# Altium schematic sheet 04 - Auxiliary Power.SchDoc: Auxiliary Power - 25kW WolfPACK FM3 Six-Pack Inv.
size 431 x 279 mm; Date: 07/2023; DocumentNumber: CRD25DA12N-FMC; Revision: 1.1; SheetNumber: 4; SheetTotal: 8; SheetSize: B
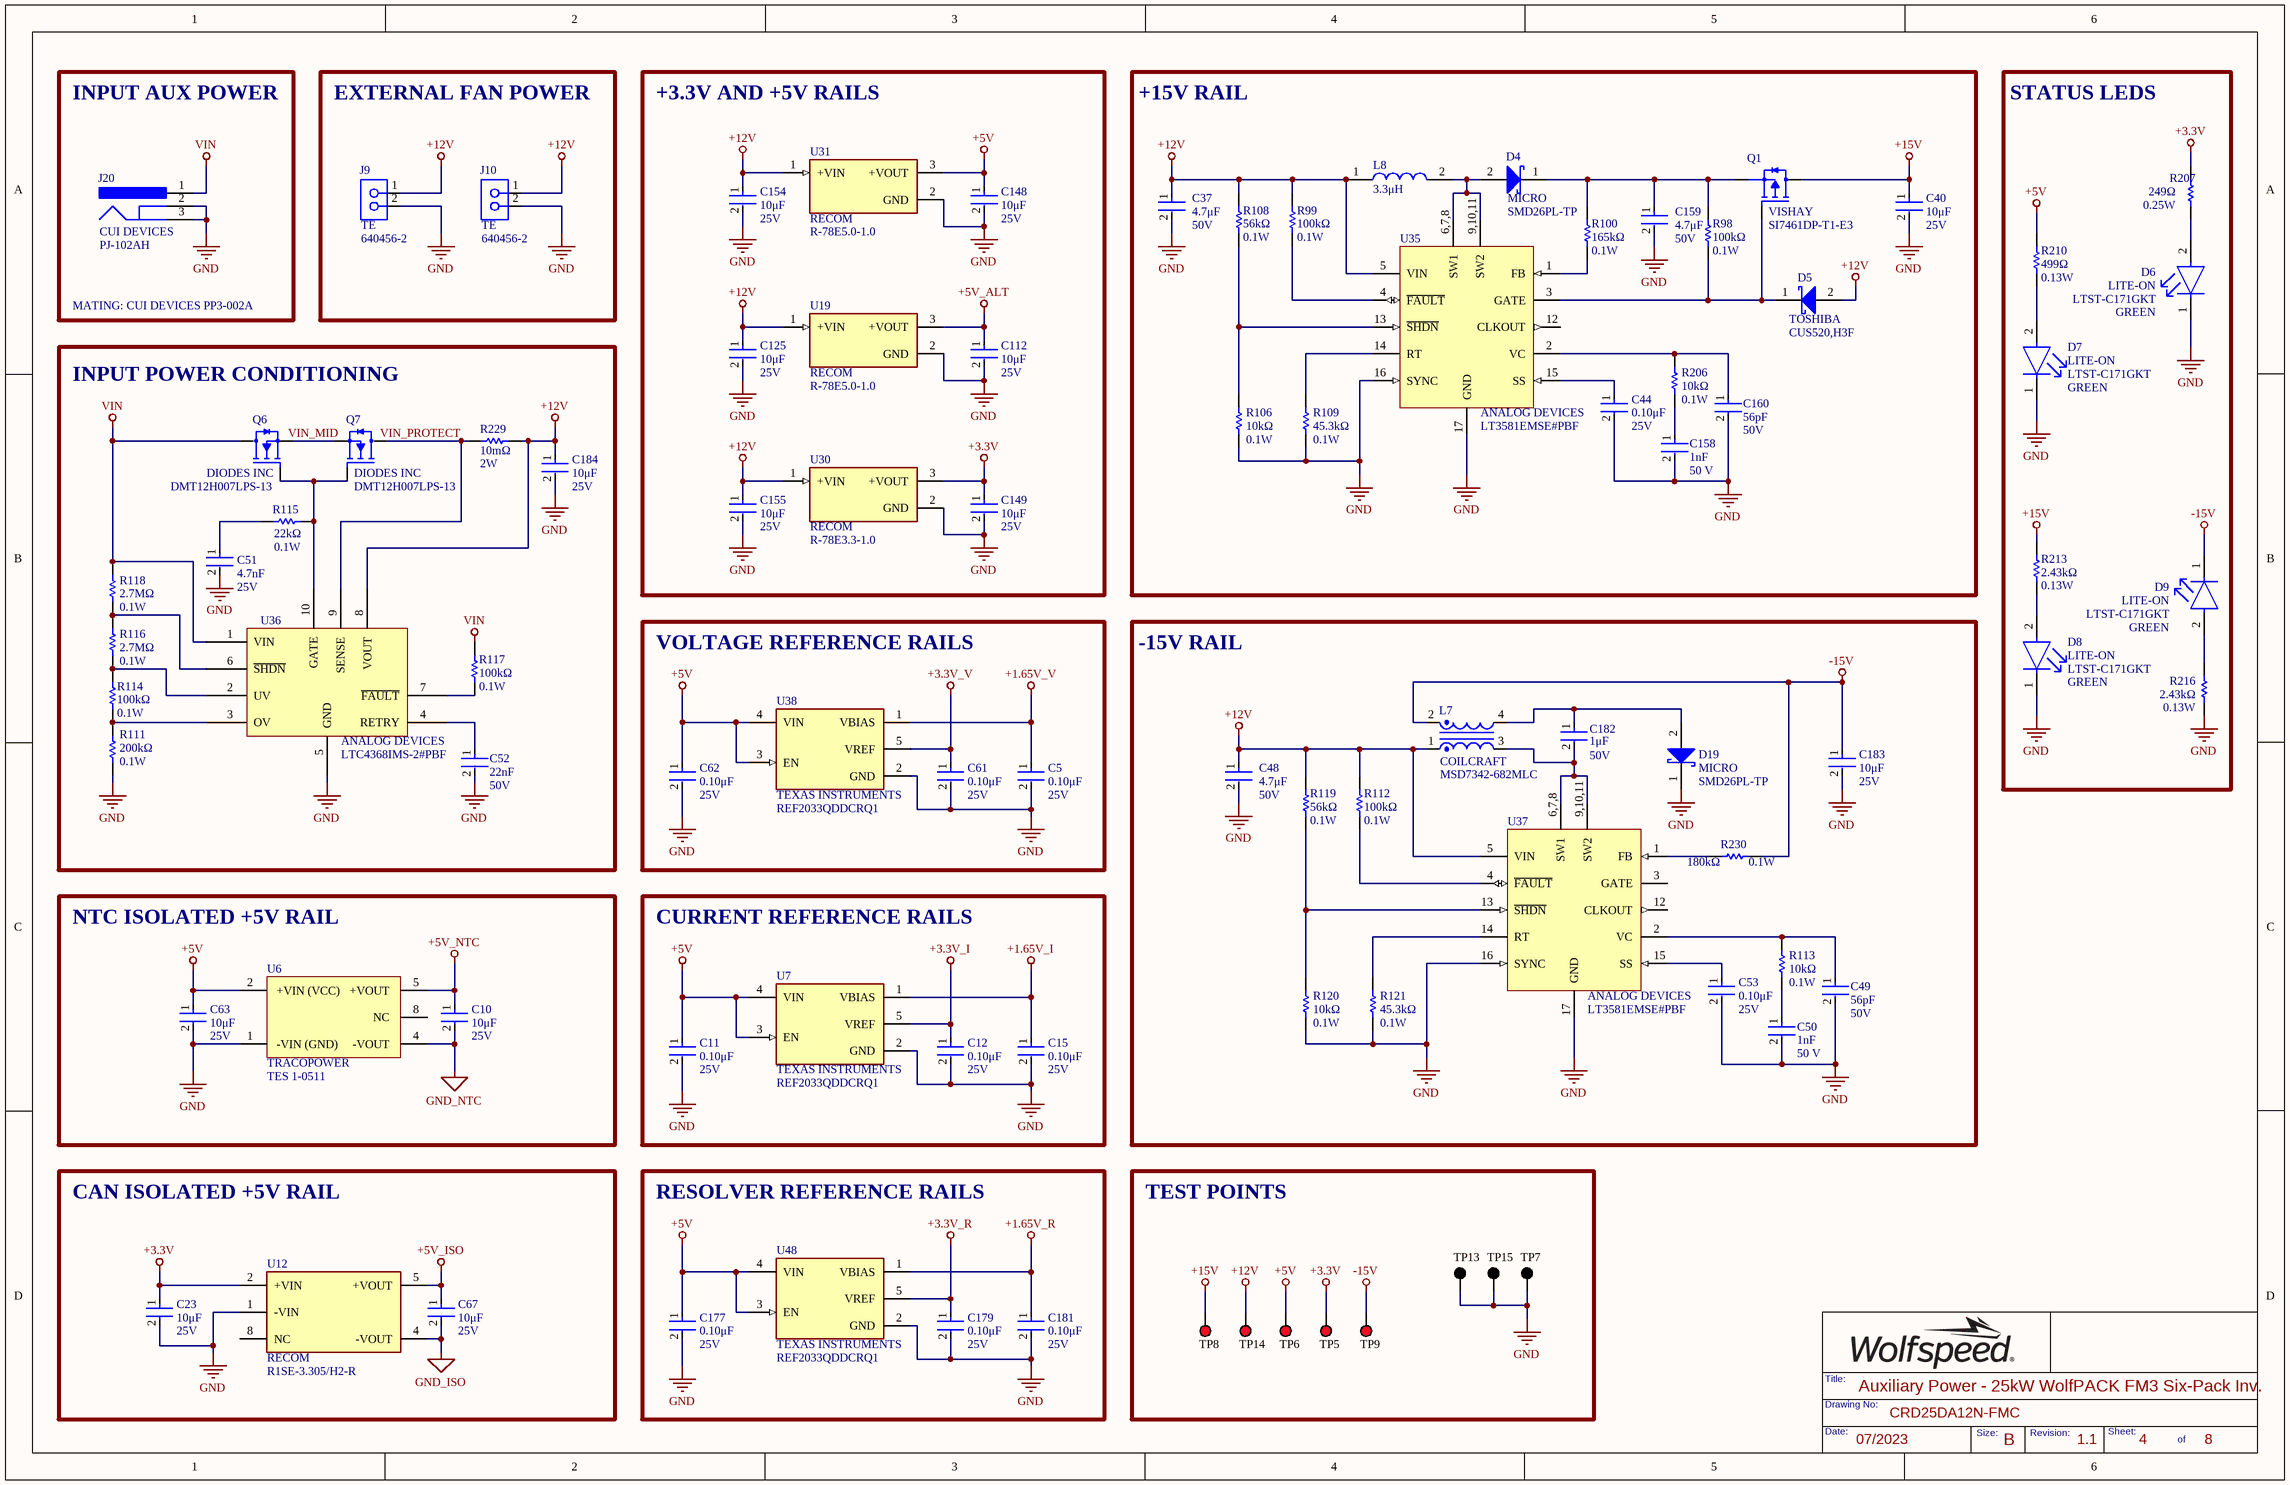
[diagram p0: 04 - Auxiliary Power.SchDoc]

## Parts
C5  Voltage Rating: 25V  Capacitance: 0.10μF  [FP-C0603C-CF-IPC_B]  (hidden comment: C0603C104K3RACTU)
C10  Voltage Rating: 25V  Capacitance: 10μF  [FP-CL31-IPC_B]  (hidden comment: CL31B106KAHSFNE)
C11  Voltage Rating: 25V  Capacitance: 0.10μF  [FP-C0603C-CF-IPC_B]  (hidden comment: C0603C104K3RACTU)
C12  Voltage Rating: 25V  Capacitance: 0.10μF  [FP-C0603C-CF-IPC_B]  (hidden comment: C0603C104K3RACTU)
C15  Voltage Rating: 25V  Capacitance: 0.10μF  [FP-C0603C-CF-IPC_B]  (hidden comment: C0603C104K3RACTU)
C23  Voltage Rating: 25V  Capacitance: 10μF  [FP-CL31-IPC_B]  (hidden comment: CL31B106KAHSFNE)
C37  Voltage Rating: 50V  Capacitance: 4.7μF  [FP-CL31-IPC_C]  (hidden comment: CL31B475KBHNFNE)
C40  Voltage Rating: 25V  Capacitance: 10μF  [FP-CL31-IPC_B]  (hidden comment: CL31B106KAHSFNE)
C44  Voltage Rating: 25V  Capacitance: 0.10μF  [FP-C0603C-CF-IPC_B]  (hidden comment: C0603C104K3RACTU)
C48  Voltage Rating: 50V  Capacitance: 4.7μF  [FP-CL31-IPC_C]  (hidden comment: CL31B475KBHNFNE)
C49  Capacitance: 56pF  Voltage Rating: 50V  [FP-C0603C-CF-IPC_B]  (hidden comment: CL10C560JB8NNNC)
C50  Capacitance: 1nF  Voltage Rating: 50 V  [FP-C0603C-CF-IPC_B]  (hidden comment: C0603C102K5RACAUTO)
C51  Voltage Rating: 25V  Capacitance: 4.7nF  [FP-C0603C-CF-IPC_B]  (hidden comment: C0603C472K3RAC7867)
C52  Capacitance: 22nF  Voltage: 50V  [FP-C0603C-CF-IPC_B]  (hidden comment: CC0805KRX7R9BB223)
C53  Voltage Rating: 25V  Capacitance: 0.10μF  [FP-C0603C-CF-IPC_B]  (hidden comment: C0603C104K3RACTU)
C61  Voltage Rating: 25V  Capacitance: 0.10μF  [FP-C0603C-CF-IPC_B]  (hidden comment: C0603C104K3RACTU)
C62  Voltage Rating: 25V  Capacitance: 0.10μF  [FP-C0603C-CF-IPC_B]  (hidden comment: C0603C104K3RACTU)
C63  Voltage Rating: 25V  Capacitance: 10μF  [FP-CL31-IPC_B]  (hidden comment: CL31B106KAHSFNE)
C67  Voltage Rating: 25V  Capacitance: 10μF  [FP-CL31-IPC_B]  (hidden comment: CL31B106KAHSFNE)
C112  Voltage Rating: 25V  Capacitance: 10μF  [FP-CL31-IPC_B]  (hidden comment: CL31B106KAHSFNE)
C125  Voltage Rating: 25V  Capacitance: 10μF  [FP-CL31-IPC_B]  (hidden comment: CL31B106KAHSFNE)
C148  Voltage Rating: 25V  Capacitance: 10μF  [FP-CL31-IPC_B]  (hidden comment: CL31B106KAHSFNE)
C149  Voltage Rating: 25V  Capacitance: 10μF  [FP-CL31-IPC_B]  (hidden comment: CL31B106KAHSFNE)
C154  Voltage Rating: 25V  Capacitance: 10μF  [FP-CL31-IPC_B]  (hidden comment: CL31B106KAHSFNE)
C155  Voltage Rating: 25V  Capacitance: 10μF  [FP-CL31-IPC_B]  (hidden comment: CL31B106KAHSFNE)
C158  Capacitance: 1nF  Voltage Rating: 50 V  [FP-C0603C-CF-IPC_B]  (hidden comment: C0603C102K5RACAUTO)
C159  Voltage Rating: 50V  Capacitance: 4.7μF  [FP-CL31-IPC_C]  (hidden comment: CL31B475KBHNFNE)
C160  Capacitance: 56pF  Voltage Rating: 50V  [FP-C0603C-CF-IPC_B]  (hidden comment: CL10C560JB8NNNC)
C177  Voltage Rating: 25V  Capacitance: 0.10μF  [FP-C0603C-CF-IPC_B]  (hidden comment: C0603C104K3RACTU)
C179  Voltage Rating: 25V  Capacitance: 0.10μF  [FP-C0603C-CF-IPC_B]  (hidden comment: C0603C104K3RACTU)
C181  Voltage Rating: 25V  Capacitance: 0.10μF  [FP-C0603C-CF-IPC_B]  (hidden comment: C0603C104K3RACTU)
C182  Capacitance: 1μF  Voltage: 50V  [FP-CL21-IPC_A]  (hidden comment: CL21B105KBFNNNE)
C183  Voltage Rating: 25V  Capacitance: 10μF  [FP-CL31-IPC_B]  (hidden comment: CL31B106KAHSFNE)
C184  Voltage Rating: 25V  Capacitance: 10μF  [FP-CL31-IPC_B]  (hidden comment: CL31B106KAHSFNE)
D4  SMD26PL-TP  Manufacturer Print: MICRO  [ONSC-SOD-123FL-2-498-01_V]
D5  CUS520,H3F  Manufacturer Print: TOSHIBA  [FP-USC-MFG]
D6  value GREEN  Manufacturer: LITE-ON  [FP-LTST-C171GKT-MFG]  (hidden comment: LTST-C171GKT)
D7  value GREEN  Manufacturer: LITE-ON  [FP-LTST-C171GKT-MFG]  (hidden comment: LTST-C171GKT)
D8  value GREEN  Manufacturer: LITE-ON  [FP-LTST-C171GKT-MFG]  (hidden comment: LTST-C171GKT)
D9  value GREEN  Manufacturer: LITE-ON  [FP-LTST-C171GKT-MFG]  (hidden comment: LTST-C171GKT)
D19  SMD26PL-TP  Manufacturer Print: MICRO  [ONSC-SOD-123FL-2-498-01_V]
J9  640456-2  Manufacturer Print: TE  [TECO-640456-2_V]
J10  640456-2  Manufacturer Print: TE  [TECO-640456-2_V]
J20  PJ-102AH  Manufacturer Print: CUI DEVICES  [CUI-PJ-102B_V]
L7  MSD7342-682MLC  Manfacturer Print: COILCRAFT  [MSD7342682MLC]
L8  value 3.3μH  [FP-NR5040-H_4_1-MFG]  (hidden comment: NRS5040T3R3NMGJ)
Q1  Manufacturer: VISHAY  [FP-S17-0173-SINGLE-MFG]  (hidden comment: SI7461DP-T1-E3)
Q6  DMT12H007LPS-13  Manufacturer: DIODES INC  [FP-PowerDI5060-8-MFG]
Q7  DMT12H007LPS-13  Manufacturer: DIODES INC  [FP-PowerDI5060-8-MFG]
R98  Resistance: 100kΩ  Power Rating: 0.1W  [FP-MCR03-IPC_B]  (hidden comment: RC0603FR-07100KL)
R99  Resistance: 100kΩ  Power Rating: 0.1W  [FP-MCR03-IPC_B]  (hidden comment: RC0603FR-07100KL)
R100  Resistance: 165kΩ  Power Rating: 0.1W  [FP-MCR03-IPC_B]  (hidden comment: ERJ-3EKF1653V)
R106  Resistance: 10kΩ  Max Power Dissipation: 0.1W  [FP-MCR03-IPC_B]  (hidden comment: ERJ3EKF1002V)
R108  Resistance: 56kΩ  Power Rating: 0.1W  [FP-MCR03-IPC_B]  (hidden comment: RC0603FR-0756KL)
R109  Max Power Dissipation: 0.1W  Resistance: 45.3kΩ  [FP-MCR03-IPC_B]  (hidden comment: RMCF0603FT45K3)
R111  Resistance: 200kΩ  Max Power Dissipation: 0.1W  [FP-MCR03-IPC_B]  (hidden comment: ERJ-3EKF2003V)
R112  Resistance: 100kΩ  Power Rating: 0.1W  [FP-MCR03-IPC_B]  (hidden comment: RC0603FR-07100KL)
R113  Resistance: 10kΩ  Max Power Dissipation: 0.1W  [FP-MCR03-IPC_B]  (hidden comment: ERJ3EKF1002V)
R114  Resistance: 100kΩ  Power Rating: 0.1W  [FP-MCR03-IPC_B]  (hidden comment: RC0603FR-07100KL)
R115  Power Rating: 0.1W  Resistance: 22kΩ  [FP-MCR03-IPC_B]  (hidden comment: ERJ-3EKF2202V)
R116  Power Rating: 0.1W  Resistance: 2.7MΩ  [FP-MCR03-IPC_B]  (hidden comment: RC0603JR-072M7L)
R117  Resistance: 100kΩ  Power Rating: 0.1W  [FP-MCR03-IPC_B]  (hidden comment: RC0603FR-07100KL)
R118  Power Rating: 0.1W  Resistance: 2.7MΩ  [FP-MCR03-IPC_B]  (hidden comment: RC0603JR-072M7L)
R119  Resistance: 56kΩ  Power Rating: 0.1W  [FP-MCR03-IPC_B]  (hidden comment: RC0603FR-0756KL)
R120  Resistance: 10kΩ  Max Power Dissipation: 0.1W  [FP-MCR03-IPC_B]  (hidden comment: ERJ3EKF1002V)
R121  Max Power Dissipation: 0.1W  Resistance: 45.3kΩ  [FP-MCR03-IPC_B]  (hidden comment: RMCF0603FT45K3)
R206  Resistance: 10kΩ  Max Power Dissipation: 0.1W  [FP-MCR03-IPC_B]  (hidden comment: ERJ3EKF1002V)
R207  Resistance: 249Ω  Power Rating: 0.25W  [FP-MCR18-IPC_A]  (hidden comment: RC1206FR-07249RL)
R210  Resistance: 499Ω  Max Power Dissipation: 0.13W  [FP-MCR10-IPC_A]  (hidden comment: RC0805FR-07499RL)
R213  Resistance: 2.43kΩ  Power Rating: 0.13W  [FP-MCR10-IPC_A]  (hidden comment: ERJ-6ENF2431V)
R216  Resistance: 2.43kΩ  Power Rating: 0.13W  [FP-MCR10-IPC_A]  (hidden comment: ERJ-6ENF2431V)
R229  Resistance: 10mΩ  Max Power Dissipation: 2W  [FP-RL2512-IPC_A]  (hidden comment: PE2512FKE7W0R01L)
R230  Resistance: 180kΩ  Max Power Dissipation: 0.1W  [FP-CRGCQ0603-IPC_A]  (hidden comment: CRGCQ0603F180K)
TP5  5010  [KSTN-5010_V]  (value not drawn)
TP6  5010  [KSTN-5010_V]  (value not drawn)
TP7  5011  [KSTN-5011_V]  (value not drawn)
TP8  5010  [KSTN-5010_V]  (value not drawn)
TP9  5010  [KSTN-5010_V]  (value not drawn)
TP13  5011  [KSTN-5011_V]  (value not drawn)
TP14  5010  [KSTN-5010_V]  (value not drawn)
TP15  5011  [KSTN-5011_V]  (value not drawn)
U6  Manufacturer: TRACOPOWER  [TRACO-TES1-5_V]  (hidden comment: TES 1-0511)
U7  Manufacturer: TEXAS INSTRUMENTS  [FP-DDC0005A-MFG]  (hidden comment: REF2033QDDCRQ1)
U12  Manufacturer: RECOM  [FP-R1SE-0505-R-MFG]  (hidden comment: R1SE-3.305/H2-R)
U19  R-78E5.0-1.0  Manufacturer Print: RECOM  [CONV_R-78E5.0-1.0]
U30  R-78E3.3-1.0  Manufacturer Print: RECOM  [CONV_R-78E3.3-1.0]
U31  R-78E5.0-1.0  Manufacturer Print: RECOM  [CONV_R-78E5.0-1.0]
U35  LT3581EMSE#PBF  Manufacturer Print: ANALOG DEVICES  [LT-MSE-16-EDP_L]
U36  LTC4368IMS-2#PBF  Manufacturer Print: ANALOG DEVICES  [SOP50P490X110-10N]
U37  LT3581EMSE#PBF  Manufacturer Print: ANALOG DEVICES  [LT-MSE-16-EDP_L]
U38  Manufacturer: TEXAS INSTRUMENTS  [FP-DDC0005A-MFG]  (hidden comment: REF2033QDDCRQ1)
U48  Manufacturer: TEXAS INSTRUMENTS  [FP-DDC0005A-MFG]  (hidden comment: REF2033QDDCRQ1)

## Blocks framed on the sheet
INPUT AUX POWER: J20
EXTERNAL FAN POWER: J9 J10
+3.3V AND +5V RAILS: C112 C125 C148 C149 C154 C155 U19 U30 U31
+15V RAIL: C37 C40 C44 C158-C160 D4 D5 L8 Q1 R98-R100 R106 R108 R109 R206 U35
STATUS LEDS: D6-D9 R207 R210 R213 R216
INPUT POWER CONDITIONING: C51 C52 C184 Q6 Q7 R111 R114-R118 R229 U36
VOLTAGE REFERENCE RAILS: C5 C61 C62 U38
-15V RAIL: C48-C50 C53 C182 C183 D19 L7 R112 R113 R119-R121 R230 U37
NTC ISOLATED +5V RAIL: C10 C63 U6
CURRENT REFERENCE RAILS: C11 C12 C15 U7
CAN ISOLATED +5V RAIL: C23 C67 U12
RESOLVER REFERENCE RAILS: C177 C179 C181 U48
TEST POINTS: TP5-TP9 TP13-TP15

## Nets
+1.65V_I: C15.1 U7.1(VBIAS)
+1.65V_R: C181.1 U48.1(VBIAS)
+1.65V_V: C5.1 U38.1(VBIAS)
+3.3V: C23.1 C149.1 R207.1 TP5.1 U12.2(+VIN) U30.3(+VOUT)
+3.3V_I: C12.1 U7.5(VREF)
+3.3V_R: C179.1 U48.5(VREF)
+3.3V_V: C61.1 U38.5(VREF)
+5V: C11.1 C62.1 C63.1 C148.1 C177.1 R210.2 TP6.1 U6.2(+VIN_(VCC)) U7.3(EN) U7.4(VIN) U31.3(+VOUT) U38.3(EN) U38.4(VIN) U48.3(EN) U48.4(VIN)
+5V_ALT: C112.1 U19.3(+VOUT)
+5V_ISO: C67.1 U12.5(+VOUT)
+5V_NTC: C10.1 U6.5(+VOUT)
+12V: C37.1 C48.1 C125.1 C154.1 C155.1 C184.1 D5.2(A) J9.1 J10.1 L7.1 L8.1 R99.2 R108.2 R112.2 R119.2 R229.2 TP14.1 U19.1(+VIN) U30.1(+VIN) U31.1(+VIN) U35.5(VIN) U36.8(VOUT) U37.5(VIN)
+15V: C40.1 Q1.5-6-7-8(D) R213.2 TP8.1
-15V: C183.1 D9.1(C) L7.2 R230.2 TP9.1
GND: C5.2 C11.2 C12.2 C15.2 C23.2 C37.2 C40.2 C44.2 C48.2 C49.2 C50.2 C51.2 C52.2 C53.2 C61.2 C62.2 C63.2 C112.2 C125.2 C148.2 C149.2 C154.2 C155.2 C158.2 C159.2 C160.2 C177.2 C179.2 C181.2 C183.2 C184.2 D6.1(C) D7.1(C) D8.1(C) D19.1(K) J9.2 J10.2 J20.2 J20.3 R106.1 R109.1 R111.1 R120.1 R121.1 R216.1 TP7.1 TP13.1 TP15.1 U6.1(-VIN_(GND)) U7.2(GND) U12.1(-VIN) U19.2(GND) U30.2(GND) U31.2(GND) U35.16(SYNC) U35.17(GND) U36.5(GND) U37.16(SYNC) U37.17(GND) U38.2(GND) U48.2(GND)
GND_ISO: C67.2 U12.4(-VOUT)
GND_NTC: C10.2 U6.4(-VOUT)
VIN: J20.1 Q6.5(D) R117.2 R118.2 U36.1(VIN)
VIN_MID: Q6.1,2,3(S) Q7.1,2,3(S)
VIN_PROTECT: Q7.5(D) R229.1 U36.9(SENSE)
NetC44_1: C44.1 U35.15(SS)
NetC49_1: C49.1 R113.2 U37.2(VC)
NetC50_1: C50.1 R113.1
NetC51_1: C51.1 R115.1
NetC52_1: C52.1 U36.4(RETRY)
NetC53_1: C53.1 U37.15(SS)
NetC158_1: C158.1 R206.1
NetC159_1: C159.1 D4.1(K) Q1.1,2,3(S) R98.2 R100.2
NetC160_1: C160.1 R206.2 U35.2(VC)
NetC182_1: C182.1 D19.2(A) L7.4
NetC182_2: C182.2 L7.3 U37.6,7,8(SW1) U37.9,10,11(SW2)
NetD4_2: D4.2(A) L8.2 U35.6,7,8(SW1) U35.9,10,11(SW2)
NetD5_1: D5.1(K) Q1.4(G) R98.1 U35.3(GATE)
NetD6_2: D6.2(A) R207.2
NetD7_2: D7.2(A) R210.1
NetD8_2: D8.2(A) R213.1
NetD9_2: D9.2(A) R216.2
NetQ6_4: Q6.4(G) Q7.4(G) R115.2 U36.10(GATE)
NetR99_1: R99.1 U35.4(~{FAULT})
NetR100_1: R100.1 U35.1(FB)
NetR106_2: R106.2 R108.1 U35.13(~{SHDN})
NetR109_2: R109.2 U35.14(RT)
NetR111_2: R111.2 R114.1 U36.3(OV)
NetR112_1: R112.1 U37.4(~{FAULT})
NetR114_2: R114.2 R116.1 U36.2(UV)
NetR116_2: R116.2 R118.1 U36.6(~{SHDN})
NetR117_1: R117.1 U36.7(~{FAULT})
NetR119_1: R119.1 R120.2 U37.13(~{SHDN})
NetR121_2: R121.2 U37.14(RT)
NetR230_1: R230.1 U37.1(FB)

Not connected (* = marked no-connect by the designer): U6 8(NC); U12 8(NC); U35 12(CLKOUT); U37 3(GATE) 12(CLKOUT)

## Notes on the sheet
- MATING: CUI DEVICES PP3-002A

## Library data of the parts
C5 C11 C12 C15 C44 C53 C61 C62 C177 C179 C181 = CMP-2006-03057-2: CAP CER 0.1UF 25V X7R 0603; Manufacturer: KEMET; Value: 0.10μF; Material: Ceramic; Tolerance: 0.1; Temperature Coefficient: 30ppm/°C; Automotive Grade: Grade 1
C10 C23 C40 C63 C67 C112 C125 C148 C149 C154 C155 C183 C184 = CMP-13271-001434-1: CAP CER 10UF 25V X7R 1206; Manufacturer: SAMSUNG; Tolerance: 10%; Value: 10μF
C37 C48 C159 = CMP-13271-001123-1: CAP CER 4.7UF 50V X7R 1206; Manufacturer: SAMSUNG; Tolerance: 10%; Value: 4.7μF
C49 C160 = CL10C560JB8NNNC: CAP CER 56PF 50V C0G/NP0 0603; Manufacturer: SAMSUNG; Material: Ceramic; Tolerance: 5%; Dielectric: C0G; Temperature Coefficient: 30ppm/°C
C50 C158 = CMP-2006-03716-2: CAP CER 1000PF 50V X7R 0603; Manufacturer: KEMET; Material: Ceramic; Automotive Grade: Grade 1; Value: 1nF; Tolerance: 0.1; Temperature Coefficient: 30ppm/°C
C51 = C0603C472K3RAC7867: CAP CER 4700PF 25V 10% X7R 0603; Manufacturer: KEMET; Manufacturer Part Number: C0603C472K3RACTU; Dielectric Material: Ceramic; Value: 4.7nF
C52 = CC0805KRX7R9BB223: CAP CER 0.022UF 50V X7R 0805; Manufacturer: YAGEO; Material: Ceramic; Tolerance: 10%; Insulation Resistance: 100GR; Value: 22nF
C182 = CL21B105KBFNNNE: CAP CER 1UF 50V X7R 0805; Manufacturer: SAMSUNG; Tolerance: 10%; Value: 1μF
D4 D19 = SMD26PL-TP: DIODE SCHOTTKY 60V 2A SOD123FL; Manufacturer: MICRO COMMERCIAL; Forward Voltage: 700mV; Max Reverse Current: 500uA; Max Surge Current: 50A; Max Power Dissipation: 1.68W
D5 = CUS520,H3F: DIODE SCHOTTKY 30V 200MA USC; Element Configuration: Single; Max Reverse Current: 5uA; Peak Non-Repetitive Surge Current: 1A
D6-D9 = CMP-22017-000007-1: LED GREEN CLEAR CHIP SMD; Luminous Intensity: 12mcd; Lens Color: Colorless; Dominant Wavelength: 569nm; Number of LEDs: 1; Power Dissipation: 100mW; Viewing Angle: 130°; Reverse Voltage: 5V; Test Current: 10mA; Forward Voltage: 2.1V; Wavelength: 585nm; Lens Style: Diffused; Forward Current: 30mA
J9 J10 = CMP-2000-05417-1: CONN HEADER VERT 2POS 2.54MM; Standards: RoHSCompliant,ELVCompliant,UL94V-0; Material, Housing: Polyester; Agency Approvals: CSA,UL; Brand/Series: MTA-100Series; Contact Centerline Spacing: 0.100 / in.; Material, Contact: CopperAlloy; Current, Rating: 5 / A; Color, Housing: White; Contact Termination Area Plating: Tin; Special Features: Pinstrip; Number of Positions: 2; Pin Spacing: 0.1 / "; Temperature, Operating: -55to+105 / degC; Angle: Straight; Mount Angle: Vertical; Connector Type: MTA-100; Primary Type: InterconnectSystem; Voltage, Rating: 250 / V; Mounting Hole Size: 0.04 / "
J20 = PJ-102AH: CONN PWR JACK 2X5.5MM SOLDER; Gender: Male; Shielding: Unshielded; Current Rating: 5A; Voltage Rating: 24V; Insulation Resistance: 50MR; Number of Conductors: 2
L7 = MSD7342-682MLC: CMC 6.8UH 2.1A 2LN 70 MOHM SMD; Core Material: Ferrite; Tolerance: 20%; DC Resistance (DCR): 70mR; Inductance - Series: 27.2uH; Value: 6.8μH
L8 = NRS5040T3R3NMGJ: FIXED IND 3.3UH 3.3A 27 MOHM SMD; Manufacturer_Name: TAIYO YUDEN; Core Material: Ferrite; Saturation Current: 4A; Shielding: Shielded; DC Resistance (DCR): 27mR; Self Resonant Frequency: 32MHz; Test Frequency: 100kHz; Tolerance: 30%
Q1 = SI7461DP-T1-E3: MOSFET P-CH 60V 8.6A PPAK SO-8; Rthja Max: 52°C/W; Max Forward Diode Voltage: -1.2V; Depletion Mode: False; Max Junction Temp: +150°C; Pulse Drain Current: -60A; Power Dissipation: 1.9W; Transconductance: 31S; Number Of Channels: 1; Gate Charge At Vgs: 121nC @ -10V; Drain To Source Resistance: 0.0115Ω; Threshold Vgs Min: -1V; Turn Off Delay Time: 205ns; Reverse Recovery Time: 45ns; Standoff Height: 0mm; Continuous Drain Current: -8.6A; Typ Forward Diode Voltage: -0.8V; Turn On Delay Time: 20ns; Gate To Source Voltage: 20V; Drain To Source Voltage: -60V; Threshold Vgs Max: -3V
Q6 Q7 = DMT12H007LPS-13: MOSFET N-CH 120V 90A PWRDI5060-8
R98 R99 R112 R114 R117 = RC0603FR-07100KL: RES 100K OHM 1% 1/10W 0603; Manufacturer: YAGEO; Temperature Coefficient: 100ppm/°C; Voltage Rating: 50V; Working Voltage: 75V; Max Power Dissipation: 100mW; Value: 100kΩ
R100 = ERJ-3EKF1653V: RES SMD 165K OHM 1% 1/10W 0603; Manufacturer: PANASONIC; Temperature Coefficient: 100ppm/°C; Voltage Rating: 75V; Max Power Dissipation: 100mW; Voltage Rating (DC): 50V; Value: 165kΩ
R106 R113 R120 R206 = ERJ3EKF1002V: RES SMD 10K OHM 1% 1/10W 0603; Manufacturer: PANASONIC; Manufacturer Part Number: ERJ-3EKF1002V; Temperature Coefficient: 100ppm/°C; Power Rating: 100mW; Voltage Rating: 75V; Value: 10kΩ
R108 R119 = RC0603FR-0756KL: RES 56K OHM 1% 1/10W 0603; Manufacturer: YAGEO; Voltage Rating (DC): 50V; Voltage Rating: 75V; Temperature Coefficient: 100ppm/°C; Max Power Dissipation: 100mW; Value: 56kΩ
R109 R121 = RMCF0603FT45K3: RES 45.3K OHM 1% 1/10W 0603; Manufacturer: STACKPOLE; Temperature Coefficient: 100ppm/°C; Value: 45.3kΩ
R111 = ERJ-3EKF2003V: RES SMD 200K OHM 1% 1/10W 0603; Manufacturer: PANASONIC; Temperature Coefficient: 100ppm/°C; Power Rating: 100mW; Voltage Rating: 75V; Voltage Rating (DC): 50V; Value: 200kΩ
R115 = CMP-2000-00337-2: RES SMD 22K OHM 1% 1/10W 0603; Manufacturer: PANASONIC; Voltage Rating: 50 V; Value: 22kΩ
R116 R118 = RC0603JR-072M7L: RES 2.7M OHM 5% 1/10W 0603; Manufacturer: YAGEO; Temperature Coefficient: 100ppm/°C; Voltage Rating: 75V; Max Power Dissipation: 100mW; Voltage Rating (DC): 50V; Value: 2.7MΩ
R207 = RC1206FR-07249RL: RES 249 OHM 1% 1/4W 1206; Manufacturer: YAGEO; Voltage Rating: 200V; Temperature Coefficient: 100ppm/°C; Max Power Dissipation: 250mW; Value: 249Ω
R210 = RC0805FR-07499RL: RES 499 OHM 1% 1/8W 0805; Manufacturer: YAGEO; Power Rating: 125mW; Voltage Rating: 150V; Temperature Coefficient: 100ppm/°C; Value: 499Ω
R213 R216 = ERJ-6ENF2431V: RES SMD 2.43K OHM 1% 1/8W 0805; Manufacturer: PANASONIC; Temperature Coefficient: 100ppm/°C; Voltage Rating: 150V; Max Power Dissipation: 125mW; Value: 2.43kΩ
R229 = PE2512FKE7W0R01L: RES 0.01 OHM 1% 2W 2512; Manufacturer: YAGEO; Temperature Coefficient: 50ppm/°C; Value: 10mΩ
R230 = CRGCQ0603F180K: RES 180K OHM 1% 1/10W 0603; Manufacturer: TE; Temperature Coefficient: 100ppm/°C; Value: 180kΩ
TP5 TP6 TP8 TP9 TP14 = CMP-1672-00002-4: PC TEST POINT MULTIPURPOSE RED; Manufacturer: KEYSTONE
TP7 TP13 TP15 = CMP-1672-00003-4: PC TEST POINT MULTIPURPOSE BLACK; Manufacturer: KEYSTONE
U6 = CMP-2000-07241-1: DC DC CONVERTER 5V 1W; DC / DC Converter Type: IsolatedPOL; SVHC: NoSVHC(16-Jun-2014); Input Voltage DC Min: 4.5V; Output Current Max: 200mA; DC / DC Converter Mounting: SMD; DC / DC Converter Output Type: Fixed; Input Voltage DC Max: 5.5V
U7 U38 U48 = REF2033QDDCRQ1: AUTOMOTIVE LOW-DRIFT, LOW-POWER,
U12 = R1SE-3.305/H2-R: DC DC CONVERTER 5V 1W; Number of Outputs: 1; Min Input Voltage: 2.97V; Max Input Voltage: 3.63V; Max Output Current: 200mA; Isolation Voltage: 2kV; Efficiency: 75%
U19 U31 = R-78E5.0-1.0: DC DC CONVERTER 5V 5W; Number of Outputs: 1; Min Input Voltage: 8V; Max Input Voltage: 28V; Max Output Current: 1A; Efficiency: 91%
U30 = R-78E3.3-1.0: DC DC CONVERTER 3.3V 3W; Number of Outputs: 1; Min Input Voltage: 8V; Max Input Voltage: 28V; Max Output Current: 1A; Efficiency: 91%; Max Output Power: 3.3W; Min Input Voltage (DC): 7V
U35 U37 = LT3581EMSE#PBF: IC REG MULTI CONFG ADJ 16MSOP; Number of Outputs: 1; Frequency Adjust Range: Up - 2.5MHz
U36 = LTC4368IMS-2#PBF: IC SURGE SUPPRESSION ADJ 10MSOP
